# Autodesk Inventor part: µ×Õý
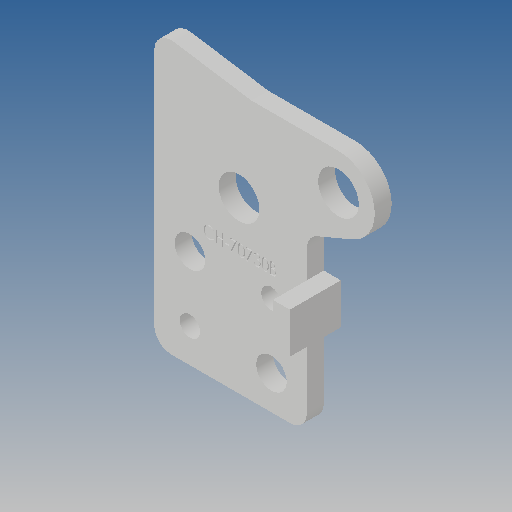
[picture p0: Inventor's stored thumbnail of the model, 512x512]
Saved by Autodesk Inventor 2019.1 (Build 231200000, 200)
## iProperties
Created: 2012-10
Part Number: µ×Õý
Material: Ogólny
Document SubType Name: Modeling
Designer: CADENGINEERING4
Density: 1 g/cm^3
Appearance: Domyślna
Author: CADENGINEERING4
Revision Number: ÈÎºÎ
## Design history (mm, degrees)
feature "À­Éì2"
node "Bryła1"
